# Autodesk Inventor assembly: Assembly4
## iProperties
Shininess: 64.0
Angle Display Precision: 2
Document Length Units: 11269
Document Angle Units: 11279
Document Time Units: 11290
Document Mass Units: 11283
Document Length Units Precision: 3
Document Angle Units Precision: 2
Created: 2002-02
Part Number: Assembly4
Document SubType Name: Assembly
Designer: ***
Density: 0.0
Volumn: 0.0
Area: 0.0
PropertySet Name: Model Information
Control State: 0
Master: False
Checked Out: False
Author: ***
